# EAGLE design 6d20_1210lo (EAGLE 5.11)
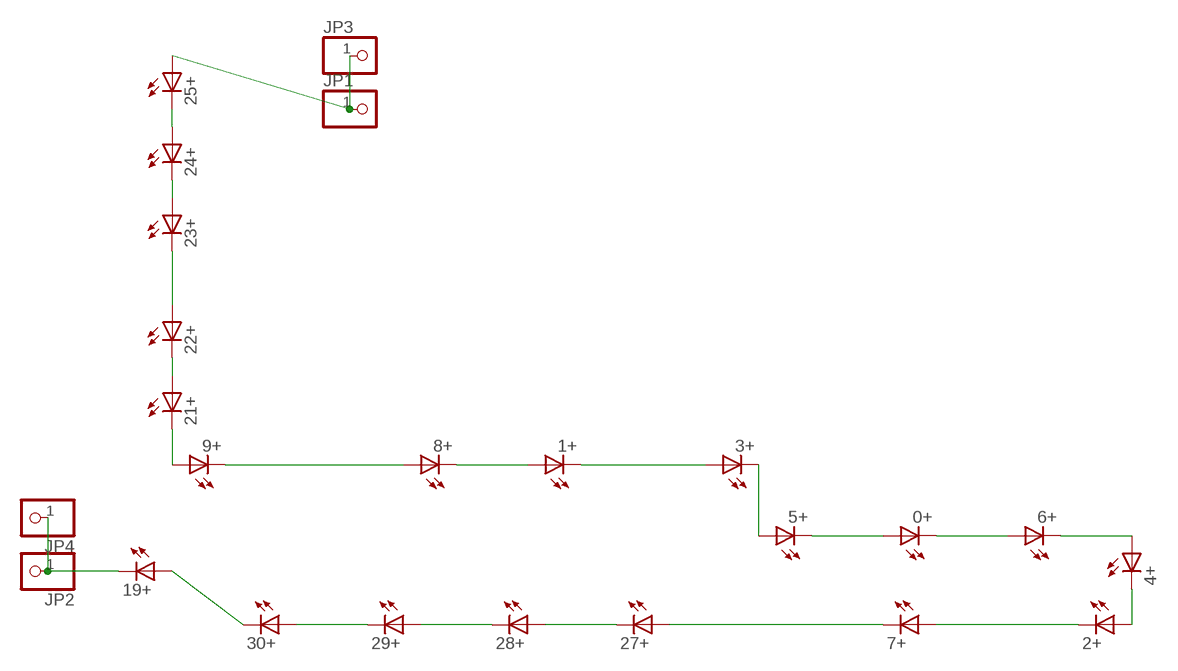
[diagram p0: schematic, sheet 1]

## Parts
0+  LED1210  [1210]
1+  LED1210  [1210]
2+  LED1210  [1210]
3+  LED1210  [1210]
4+  LED1210  [1210]
5+  LED1210  [1210]
6+  LED1210  [1210]
7+  LED1210  [1210]
8+  LED1210  [1210]
9+  LED1210  [1210]
19+  LED1210  [1210]
21+  LED1210  [1210]
22+  LED1210  [1210]
23+  LED1210  [1210]
24+  LED1210  [1210]
25+  LED1210  [1210]
27+  LED1210  [1210]
28+  LED1210  [1210]
29+  LED1210  [1210]
30+  LED1210  [1210]
JP1  PINHD-1X11MM6  [1X1MM8]
JP2  PINHD-1X11MM6  [1X1MM8]
JP3  PINHD-1X11X0.4  [1X01]
JP4  PINHD-1X11X0.4  [1X01]

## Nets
MINUS: 19+.P$2(C) JP2.1 JP4.1
N$4: 19+.P$1(A) 30+.P$2(C)
N$6: 8+.P$1(A) 9+.P$2(C)
N$7: 29+.P$2(C) 30+.P$1(A)
N$8: 28+.P$2(C) 29+.P$1(A)
N$9: 27+.P$2(C) 28+.P$1(A)
N$12: 2+.P$2(C) 7+.P$1(A)
N$13: 7+.P$2(C) 27+.P$1(A)
N$14: 2+.P$1(A) 4+.P$2(C)
N$15: 4+.P$1(A) 6+.P$2(C)
N$16: 0+.P$2(C) 6+.P$1(A)
N$17: 0+.P$1(A) 5+.P$2(C)
N$18: 3+.P$2(C) 5+.P$1(A)
N$19: 1+.P$2(C) 3+.P$1(A)
N$20: 1+.P$1(A) 8+.P$2(C)
N$23: 9+.P$1(A) 21+.P$2(C)
N$24: 21+.P$1(A) 22+.P$2(C)
N$25: 22+.P$1(A) 23+.P$2(C)
N$26: 24+.P$1(A) 25+.P$2(C)
N$28: 23+.P$1(A) 24+.P$2(C)
PLUS: 25+.P$1(A) JP1.1 JP3.1

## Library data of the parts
0+ 1+ 2+ 3+ 4+ 5+ 6+ 7+ 8+ 9+ 19+ 21+ 22+ 23+ 24+ 25+ 27+ 28+ 29+ 30+ = led(2):LED: LED
JP1-JP4 = pinhead:PINHD-1X1: PIN HEADER

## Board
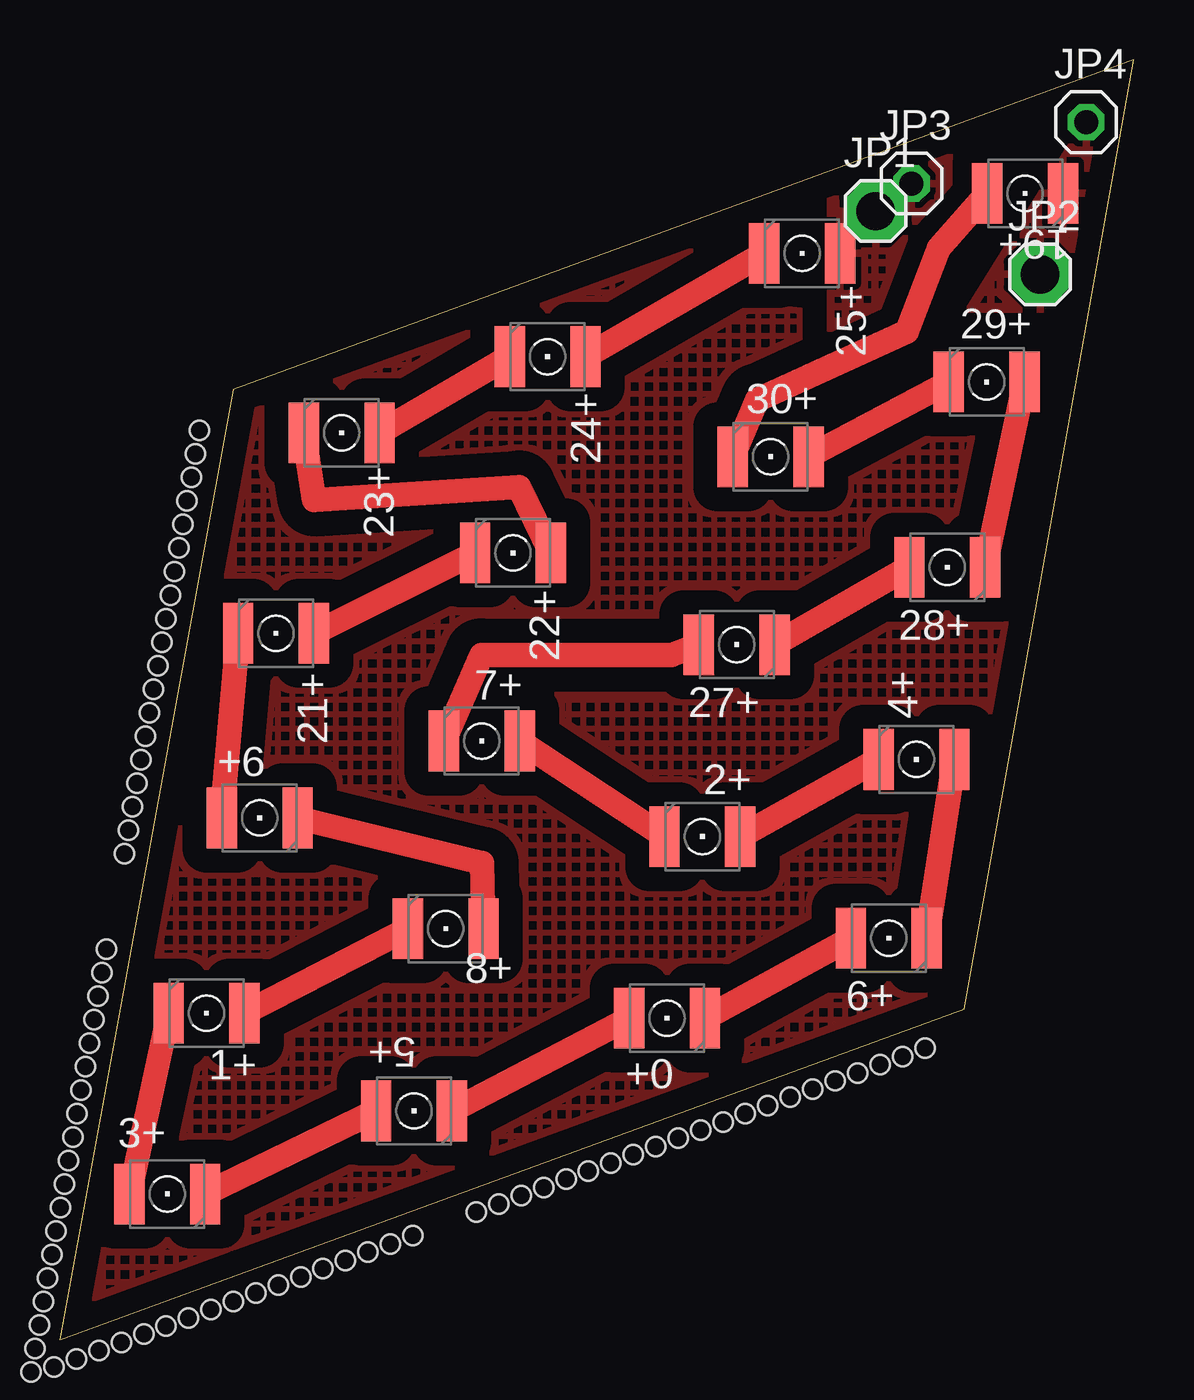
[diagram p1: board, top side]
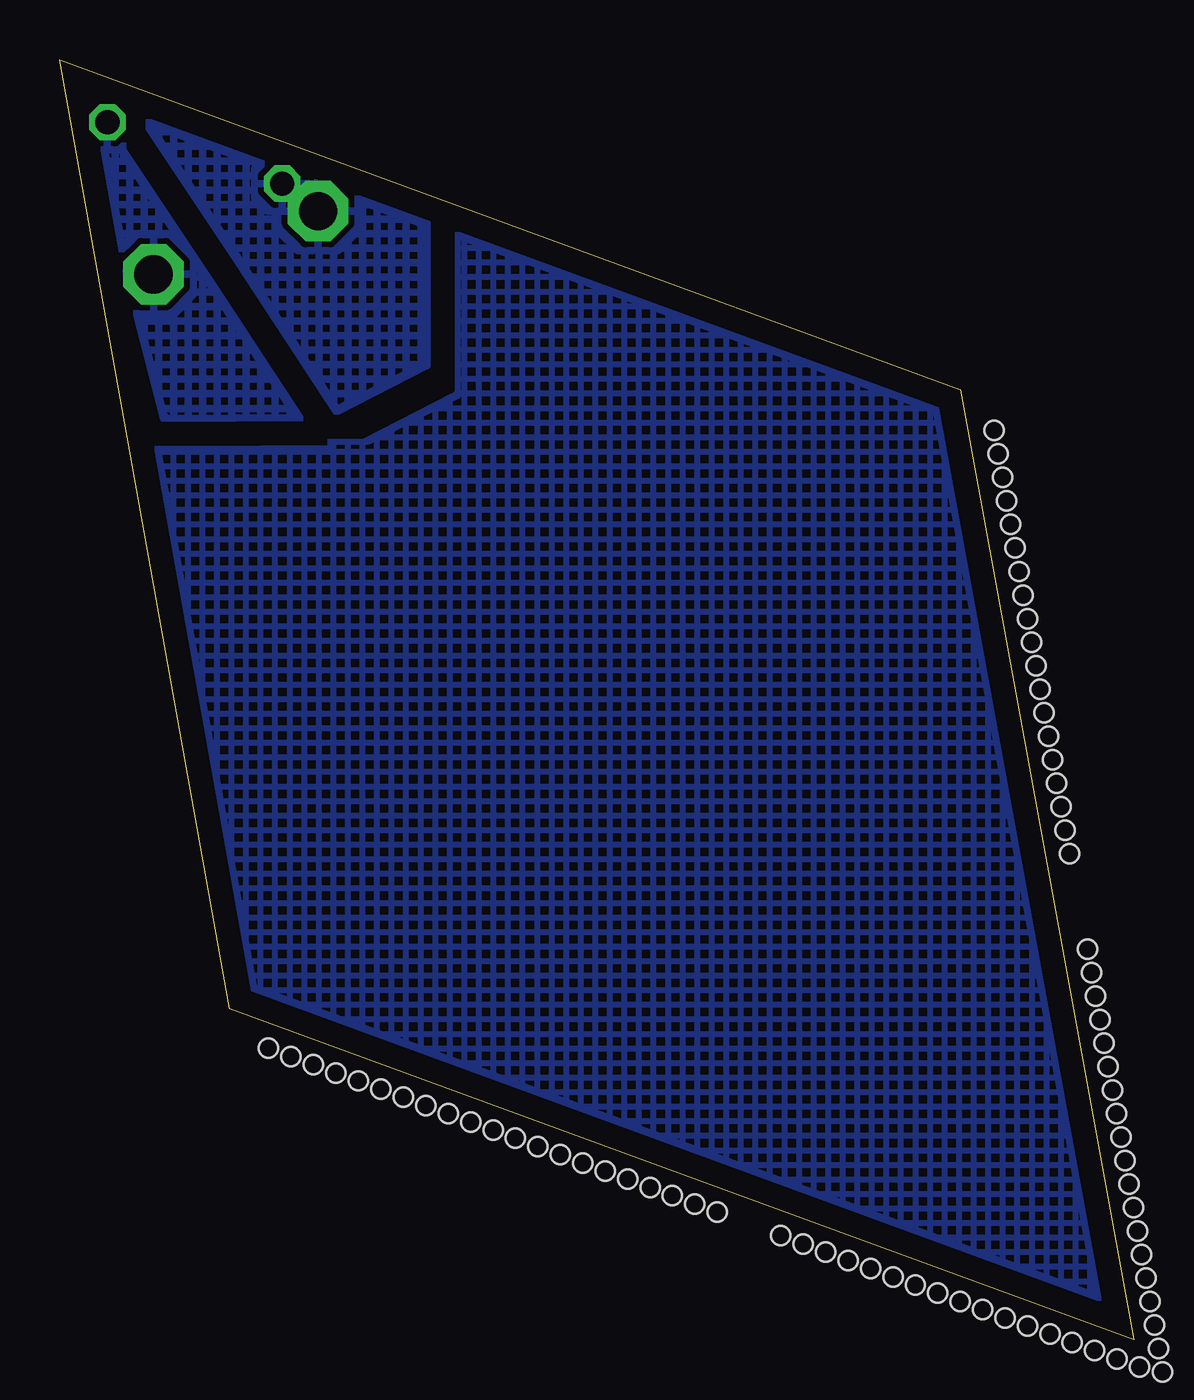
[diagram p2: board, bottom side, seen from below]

Size 45 x 53.62 mm. Coordinates in mm from the lower left corner, seen from the top.
Outline: 0,0 37.89,13.87 45,53.62 7.27,39.8 0,0
Copper layers (1*16): Top 0.035mm / dielectric 1.5mm / Bottom 0.035mm
Design rules "default": minimum track width 10mil, minimum drill 24mil, track to track 8mil, track to pad 8mil, pad to pad 8mil, via to via 8mil, smd to smd 8mil, copper to edge 40mil, drill to drill 8mil, minimum pad ring 10mil, minimum via ring 8mil, stop-mask expansion 4mil, vias tented up to drill 0mil, thermal gap 10mil
Holes 0.8 mm at 2.71,20.37 2.88,21.35 3.06,22.34 3.23,23.32 3.41,24.3 3.58,25.29 3.76,26.27 3.93,27.26 4.11,28.24 4.28,29.23 4.46,30.21 4.63,31.2 4.81,32.18 4.99,33.16 5.16,34.15 5.34,35.13 5.51,36.12 5.69,37.1 5.86,38.09 -1.2,-1.35 -1.03,-0.37 -0.85,0.61 -0.68,1.6 -0.5,2.58 -0.33,3.57 -0.15,4.55 0.02,5.54 0.2,6.52 0.37,7.51 0.55,8.49 0.72,9.48 0.9,10.46 1.08,11.44 1.25,12.43 1.43,13.41 1.6,14.4 1.78,15.38 1.95,16.37 14.79,4.36 13.85,4.01 12.91,3.67 11.97,3.33 11.03,2.98 10.1,2.64 9.16,2.29 8.22,1.95 7.28,1.61 6.34,1.26 5.4,0.92 4.46,0.58 3.52,0.23 2.58,-0.11 1.64,-0.45 0.7,-0.8 -0.23,-1.14 32.48,10.85 31.54,10.5 30.6,10.16 29.66,9.82 28.72,9.47 27.79,9.13 26.85,8.78 25.91,8.44 24.97,8.1 24.03,7.75 23.09,7.41 22.15,7.07 21.21,6.72 20.27,6.38 19.33,6.04 18.39,5.69 17.46,5.35 36.25,12.21 35.31,11.87 34.37,11.52 33.44,11.18

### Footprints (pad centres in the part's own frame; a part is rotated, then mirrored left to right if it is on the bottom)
1210 = smd 1.27 x 2.54: P$1 1.587,0; P$2 -1.587,0
1X1MM8 = drill 1.6 pad 2.54 octagon: 1 0,0
1X01 = drill 1.016 octagon: 1 0,0

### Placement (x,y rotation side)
0+  25.44,13.47 180 top
1+  6.15,13.68 0 top
2+  26.92,21.08 0 top
3+  4.51,6.11 180 top
4+  35.89,24.31 0 top
5+  14.84,9.59 180 top
6+  34.73,16.82 180 top
7+  17.68,25.08 0 top
8+  16.17,17.22 0 top
9+  8.38,21.86 180 top
19+  40.44,48.02 180 top
21+  9.06,29.59 0 top
22+  18.99,32.96 0 top
23+  11.81,37.99 0 top
24+  20.44,41.18 0 top
25+  31.1,45.51 0 top
27+  28.36,29.12 180 top
28+  37.18,32.36 180 top
29+  38.83,40.12 0 top
30+  29.78,36.99 0 top
JP1  34.18,47.28 0 top
JP2  41.07,44.63 0 top
JP3  35.68,48.43 0 top
JP4  43,51 0 top

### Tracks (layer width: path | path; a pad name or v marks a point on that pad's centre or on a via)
MINUS
  pour Top (isolate 0.813, rank 2, hatched): 44.45,53.34 38.1,43.18 43.18,43.18
  pour Bottom (isolate 0.813, rank 2, hatched): 44.45,53.34 34.58,38.63 40.64,38.58
N$1
  pour Top (isolate 1.016, rank 3, hatched): 6.35,39.37 0,0 38.1,13.97 41.91,41.91 30.48,43.18 29.21,46.99
  pour Bottom (isolate 1.016, rank 3, hatched): 6.35,39.37 0,0 38.1,13.97 41.91,41.91 30.48,43.18 29.21,46.99
N$4
  Top 1.016: 30+.P$2 29.21,39.37 35.48,42.23 36.83,45.72 19+.P$1
N$6
  Top 1.016: 8+.P$1 17.7,19.97 9+.P$2
N$7
  Top 1.016: 30+.P$1 29+.P$2
N$8
  Top 1.016: 28+.P$2 29+.P$1
N$9
  Top 1.016: 27+.P$2 28+.P$1
N$12
  Top 1.016: 7+.P$1 2+.P$2
N$13
  Top 1.016: 7+.P$2 17.67,28.69 25.63,28.68 27+.P$1
N$14
  Top 1.016: 2+.P$1 4+.P$2
N$15
  Top 1.016: 6+.P$2 4+.P$1
N$16
  Top 1.016: 0+.P$2 6+.P$1
N$17
  Top 1.016: 5+.P$2 0+.P$1
N$18
  Top 1.016: 3+.P$2 5+.P$1
N$19
  Top 1.016: 3+.P$1 1+.P$2
N$20
  Top 1.016: 1+.P$1 8+.P$2
N$23
  Top 1.016: 9+.P$1 21+.P$2
N$24
  Top 1.016: 21+.P$1 22+.P$2
N$25
  Top 1.016: 22+.P$1 19.25,35.72 10.66,35.18 23+.P$2
N$26
  Top 1.016: 24+.P$1 25+.P$2
N$28
  Top 1.016: 23+.P$1 24+.P$2
PLUS
  pour Top (isolate 0.813, hatched): 39.37,50.8 36.83,46.99 35.56,42.29 32.29,42.29 32.29,48.64
  pour Bottom (isolate 0.813, hatched): 42.27,52.28 37.5,45.11 33.41,38.85 29.6,40.81 29.6,47.16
